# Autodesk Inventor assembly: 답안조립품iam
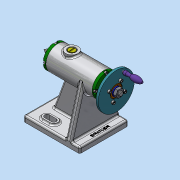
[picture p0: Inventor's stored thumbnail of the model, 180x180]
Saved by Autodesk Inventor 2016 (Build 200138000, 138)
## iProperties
Created: 2019-10
Part Number: 답안조립품iam
Material: 일반
Document SubType Name: Assembly
Designer: Administrator
Author: Administrator
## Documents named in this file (18)
- C:\Users\Administrator\Desktop\491004V1021\답안조립품iam.iam
- C:\Users\Administrator\Desktop\491004V1021\본체.ipt
- C:\Users\Administrator\Desktop\491004V1021\슬리브.ipt
- C:\Users\Administrator\Desktop\491004V1021\센터홀더.ipt
- C:\Users\Administrator\Desktop\491004V1021\중공축.ipt
- C:\Users\Administrator\Desktop\491004V1021\볼트 M3.ipt
- C:\Users\Administrator\Desktop\491004V1021\센터.ipt
- C:\Users\Administrator\Desktop\491004V1021\멈춤나사 M3.ipt
- C:\Users\Administrator\Desktop\491004V1021\나사.ipt
- C:\Users\Administrator\Desktop\491004V1021\나사축.ipt
- C:\Users\Administrator\Desktop\491004V1021\부시.ipt
- C:\Users\Administrator\Desktop\491004V1021\커버.ipt
- C:\Users\Administrator\Desktop\491004V1021\키 4 x 4 x 10.ipt
- C:\Users\Administrator\Desktop\491004V1021\플랜지.ipt
- C:\Users\Administrator\Desktop\491004V1021\와셔.ipt
- C:\Users\Administrator\Desktop\491004V1021\너트 M8.ipt
- C:\Users\Administrator\Desktop\491004V1021\돌림판.ipt
- C:\Users\Administrator\Desktop\491004V1021\핸들.ipt
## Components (2 placed, 2 different names)
1. 플랜지:1
2. 핸들:1
